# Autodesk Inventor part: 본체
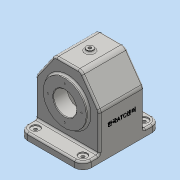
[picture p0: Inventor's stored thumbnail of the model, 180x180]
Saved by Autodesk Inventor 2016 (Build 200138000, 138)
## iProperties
Created: 2022-12
Part Number: 본체
Material: 일반
Document SubType Name: Modeling
Designer: 하동건
Density: 1 g/cm^3
Appearance: 기본값
Mass: 347.033 g
Surface Area: 1065.53 cm^2
Volume: 347.033 cm^3
Author: 하동건
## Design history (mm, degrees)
sketch "스케치1"
  geometry: L1 (0, 0)-(0, 110); L2 (0, 0)-(55, 0); L3 (55, 0)-(55, 65); L4 (55, 65)-(23.491, 110); L5 (0, 110)-(23.491, 110); L6 (0, 0)-(-55, 0); L7 (-55, 0)-(-55, 65); L8 (-55, 65)-(-23.491, 110); L9 (0, 110)-(-23.491, 110)
  constraints: 18 end point, 3 symmetric about line, 2 horizontal, 1 perpendicular, 1 vertical
  dimensions: "d0" = 110 distance of L1.start L1.end; "d1" = 55 distance of L1.start L2.end; "d2" = 65 distance of L2.end L3.end; "d3" = 35 deg angle of L3 L4
extrude "돌출1" new body sketch "스케치1" stored distance "d4" = 77; taper "d5" = 0 deg
feature "쉘2" dims "d20" = 5
sketch "스케치10"
  geometry: L1 (110, 28.5)-(0, 28.5); L2 (0, 28.5)-(0, -105.5); L3 (0, -105.5)-(110, -105.5); L4 (110, -105.5)-(110, 28.5); L5 (110, 28.5)-(0, -105.5); L6 (0, 28.5)-(110, -105.5); 1 further point
  constraints: 12 end point, 2 midpoint, 2 parallel, 1 horizontal, 1 perpendicular
  dimensions: "d21" = 110 distance of L2.end L3.end; "d22" = 134 distance of L1.end L2.end
extrude "돌출3" join sketch "스케치10" distance "d23" = 12; taper "d24" = 0 deg
sketch "스케치11"
  geometry: L1 (5, -72)-(105, -72); L2 (105, -72)-(105, -5); L3 (105, -5)-(5, -5); L4 (5, -5)-(5, -72); L5 (5, -72)-(105, -5); L6 (105, -72)-(5, -5); L7 (110, -77)-(110, 0) reference; L8 (110, 0)-(110, 28.5) reference; L9 (110, -105.5)-(110, 28.5) reference; L10 (110, -105.5)-(110, -77) reference; 1 further point
  constraints: 12 end point, 2 midpoint, 2 parallel, 1 horizontal, 1 perpendicular
  dimensions: "d25" = 67 distance of L1.end L2.end; "d26" = 5 distance between parallel lines of L2 L7
extrude "돌출4" cut sketch "스케치11" distance "d27" = 12; taper "d28" = 0 deg
sketch "스케치12"
  geometry: L1 (-33.5, -12)-(-33.5, 12); L2 (-33.5, 12)-(-19.5, 26); L3 (-38.5, 65)-(-38.5, 0) reference; L4 (38.5, 0)-(38.5, 65) reference; L5 (-38.5, 53)-(38.5, 53); L6 (-19.5, 26)-(-19.5, 53); L7 (-33.5, 12)-(-33.5, 53); L8 (33.5, -12)-(-33.5, -12) reference; L9 (0, -12)-(-33.5, -12); L10 (-33.5, -12)-(-33.5, 12); L11 (-33.5, 63.424)-(-33.5, -12) reference; L12 (-33.5, 12)-(-33.5, 53); 1 further point
  constraints: 16 end point, 5 point on line, 1 collinear, 1 horizontal, 1 perpendicular, 1 vertical
  dimensions: "d31" = 19 distance from line of L3 L2.end; "d32" = 54 diameter of L2.end L5; "d120" = 135 deg angle of L1 L2; "d121" = 65 distance between parallel lines of L8 L5
revolve "회전1" sketch "스케치12" stored, may be unused: angle "d35" = 90 deg
sketch "스케치13"
  geometry: L1 (-50, -12)-(50, -12) reference; L2 (0, -12)-(0, 53); C1 r 37.5 at (0, 53); 1 further point
  constraints: 2 end point, 1 centre point, 1 coincident, 1 midpoint, 1 vertical
  dimensions: "d36" = 65 distance of L2.start L2.end; "d37" = 75 diameter of C1
extrude "돌출5" join sketch "스케치13" distance "d38" = 5; taper "d39" = 0 deg
sketch "스케치14"
  geometry: C1 r 20 at (0, 0); 1 further point
  constraints: 1 centre point
  dimensions: "d40" = 40 diameter of C1
sketch "스케치15"
  geometry: L1 (-50, 12)-(50, 12) reference; L2 (0, 12)-(0, -53); C1 r 41 at (0, -53) reference; C2 r 31 at (0, -53); 1 further point
  constraints: 2 end point, 1 centre point, 1 coincident, 1 midpoint, 1 perpendicular
  dimensions: "d41" = 65 distance of L2.start L2.end (derived); "d43" = 62 diameter of C2
extrude "돌출6" join sketch "스케치15" distance "d44" = 10; taper "d45" = 0 deg
extrude "돌출7" cut sketch "스케치14" stored distance "d46" = 10; taper "d47" = 0 deg
node "작업 평면1"
sketch "스케치16"
  geometry: C1 r 6 at (55, -38.5); 1 further point
  constraints: 1 centre point, 1 coincident
  dimensions: "d49" = 12 diameter of C1
extrude "돌출8" join sketch "스케치16" stored distance "d50" = 10; taper "d51" = 0 deg
sketch "스케치17"
  geometry: C1 r 6 at (0, 0) reference; 2 further points
  constraints: 1 coincident
hole "구멍1" sketch "스케치17" at (0, 0) diameter "d52" = 5.188; stored, may be unused: countersink angle "d56" = 90 deg, drill point angle "d58" = 118 deg; dims "d53" = 12, "d54" = 4, "d55" = 2, "d57" = 16
fillet "모깎기1" dims "d62" = 3
chamfer "모따기2" distance "d63" = 1; stored, may be unused: second distance "d64" = 2, angle "d65" = 45 deg
chamfer "모따기3" distance "d66" = 1; stored, may be unused: second distance "d67" = 2, angle "d68" = 45 deg
fillet "모깎기2" dims "d69" = 3
fillet "모깎기3" dims "d70" = 10
fillet "모깎기4" dims "d71" = 10
sketch "스케치18"
  geometry: L1 (0, 0)-(0, 29); C1 r 37.5 at (0, 0) reference; C2 r 21 at (0, 0) reference; 1 further point
  constraints: 2 end point, 1 vertical
  dimensions: "d73" = 29 distance of L1.start L1.end
hole "구멍2" sketch "스케치18" at (0, 29) diameter "d74" = 2.459; stored, may be unused: countersink angle "d78" = 90 deg, drill point angle "d80" = 118 deg; dims "d75" = 6, "d76" = 4, "d77" = 2, "d79" = 8
sketch "스케치19"
  geometry: L1 (0, 0)-(0, -26); C1 r 27 at (0, 0) reference; 1 further point
  constraints: 2 end point, 1 vertical
  dimensions: "d84" = 26 distance of L1.start L1.end
hole "구멍3" sketch "스케치19" at (0, -26) diameter "d85" = 2.459; stored, may be unused: countersink angle "d89" = 90 deg, drill point angle "d91" = 118 deg; dims "d86" = 6, "d87" = 4, "d88" = 2, "d90" = 8
fillet "모깎기5" dims "d95" = 14
sketch "스케치21"
  geometry: C1 r 7.5 at (-14, -91.5); A1 r 14 centre (-14, -91.5) between (-14, -105.5) and (0, -91.5) reference; 1 further point
  constraints: 1 centre point, 1 coincident
  dimensions: "d96" = 15 diameter of C1
extrude "돌출9" cut sketch "스케치21" distance "d97" = 2; taper "d98" = 0 deg
sketch "스케치22"
  geometry: L1 (0, -14)-(-82, -14) reference; L2 (14, 14.5)-(14, 0) reference; L3 (-96, 14.5)-(14, 14.5) reference; L4 (-96, 0)-(-96, 14.5) reference; L5 (-96, 91.5)-(-96, 106) reference; L6 (14, 91.5)-(-96, 91.5) reference; L7 (14, 106)-(14, 91.5) reference; L8 (-82, 120)-(0, 120) reference; C1 r 2.75 at (0, 0); C2 r 7.5 at (0, 0) reference; A1 r 14 centre (-82, 0) between (-96, 0) and (-82, -14) reference; A2 r 14 centre (0, 0) between (0, -14) and (14, 0) reference; A3 r 14 centre (-82, 106) between (-82, 120) and (-96, 106) reference; A4 r 14 centre (0, 106) between (14, 106) and (0, 120) reference; 1 further point
  constraints: 1 centre point
  dimensions: "d99" = 5.5 diameter of C1
extrude "돌출10" cut sketch "스케치22" stored distance "d100" = 2; taper "d101" = 0 deg
sketch "스케치23"
  geometry: L1 (-14, -105.5)-(-96, -105.5) reference; L2 (0, -77)-(0, -91.5) reference; L3 (-110, -77)-(0, -77) reference; L4 (-110, -91.5)-(-110, -77) reference; L5 (-110, 0)-(-110, 14.5) reference; L6 (0, 0)-(-110, 0) reference; L7 (0, 14.5)-(0, 0) reference; L8 (-96, 28.5)-(-14, 28.5) reference; C1 r 7.5 at (-14, -91.5) reference; C2 r 7.5 at (-96, -91.5); C3 r 7.5 at (-96, 14.5); C4 r 7.5 at (-14, 14.5); A1 r 14 centre (-96, -91.5) between (-110, -91.5) and (-96, -105.5) reference; A2 r 14 centre (-14, -91.5) between (-14, -105.5) and (0, -91.5) reference; A3 r 14 centre (-96, 14.5) between (-96, 28.5) and (-110, 14.5) reference; A4 r 14 centre (-14, 14.5) between (0, 14.5) and (-14, 28.5) reference; 1 further point
  constraints: 3 centre point, 3 coincident
  dimensions: "d102" = 15 diameter of C2; "d103" = 15 diameter of C3; "d104" = 15 diameter of C4
extrude "돌출11" cut sketch "스케치23" distance "d105" = 2; taper "d106" = 0 deg
sketch "스케치24"
  geometry: C1 r 2.75 at (0, 0); C2 r 7.5 at (0, 106) reference; C3 r 7.5 at (82, 106) reference; C4 r 7.5 at (0, 106) reference; C5 r 2.75 at (0, 106); C6 r 2.75 at (82, 106); 1 further point
  constraints: 3 centre point, 2 coincident
  dimensions: "d107" = 5.5 diameter of C1; "d108" = 5.5 diameter of C5; "d109" = 5.5 diameter of C6
extrude "돌출12" cut sketch "스케치24" stored distance "d110" = 2; taper "d111" = 0 deg
fillet "모깎기6" dims "d112" = 3
fillet "모깎기7" dims "d113" = 3
fillet "모깎기8" dims "d114" = 3
node "작업 평면2"
sketch "스케치25"
  geometry: L1 (-67, -3)-(-67, -12) reference; L2 (53, -12)-(-53, -12) reference; 2 further points
  constraints: 1 other
  dimensions: "d116" = 67 distance from line of L1 point (0, 38); "d117" = 50 distance from line of L2 point (0, 38)
feature "엠보싱1" sketch "스케치25" dims "d118" = 0.5, "d119" = 0
fillet "모깎기9" dims "d122" = 3
fillet "모깎기10" dims "d123" = 3
fillet "모깎기11" dims "d124" = 3
fillet "모깎기12" dims "d125" = 3
feature "분할1"
node "솔리드1"
pattern_circular "원형 패턴1" dims angle "d82" = 360 deg
pattern_circular "원형 패턴2" dims angle "d93" = 360 deg
node "투영된 루프3"
node "투영된 루프4"
node "투영된 루프5"
node "투영된 루프6"
node "투영된 루프7"
node "투영된 루프8"
node "투영된 루프9"
node "투영된 루프10"
node "투영된 루프11"
other parameters: "d48" = -126, "d115" = 77
